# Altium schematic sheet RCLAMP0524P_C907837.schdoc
size 127 x 101 mm
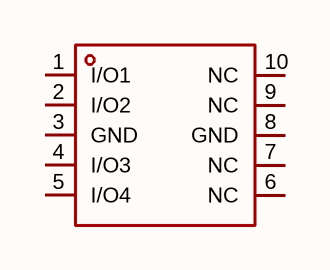
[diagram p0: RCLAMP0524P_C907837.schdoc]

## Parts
D?  rclamp0524p_c907837  [DFN2510-10_L2.5-W1.0-P0.50-BL]  (value not drawn)

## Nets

Not connected (* = marked no-connect by the designer): D? 1(I/O1) 2(I/O2) 3(GND) 4(I/O3) 5(I/O4) 6(NC) 7(NC) 8(GND) 9(NC) 10(NC)

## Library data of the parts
D? = rclamp0524p_c907837: 极性:单向;反向截止电压(Vrwm):5V;钳位电压:17V;峰值脉冲电流(Ipp):4.5A;峰值脉冲功率(Ppp):-;击穿电压(VBR):6.8V;; Manufacturer: TECH PUBLIC(台舟); AddInBom: yes; ModelId: 55525fa8fc914f7c8ffcb10749ea5f73; ModelName: DFN-10_L2.5-W1.0-H0.5-P0.50; ModelTransform: 40.1574,98.425,0,90,0,0,0,0,0; Polarity: 单向; Reverse Stand-Off Voltage (Vrwm): 5V; Clamping Voltage: 17V; Peak Pulse Current (Ipp): 4.5A; Voltage - Breakdown: 6.8V; Reverse Leakage Current (Ir): 80nA; Number of Channels: 四路; level of protection: IEC 61000-4-2; Type: ESD; Junction Capacitance: 0.35pF；0.8pF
